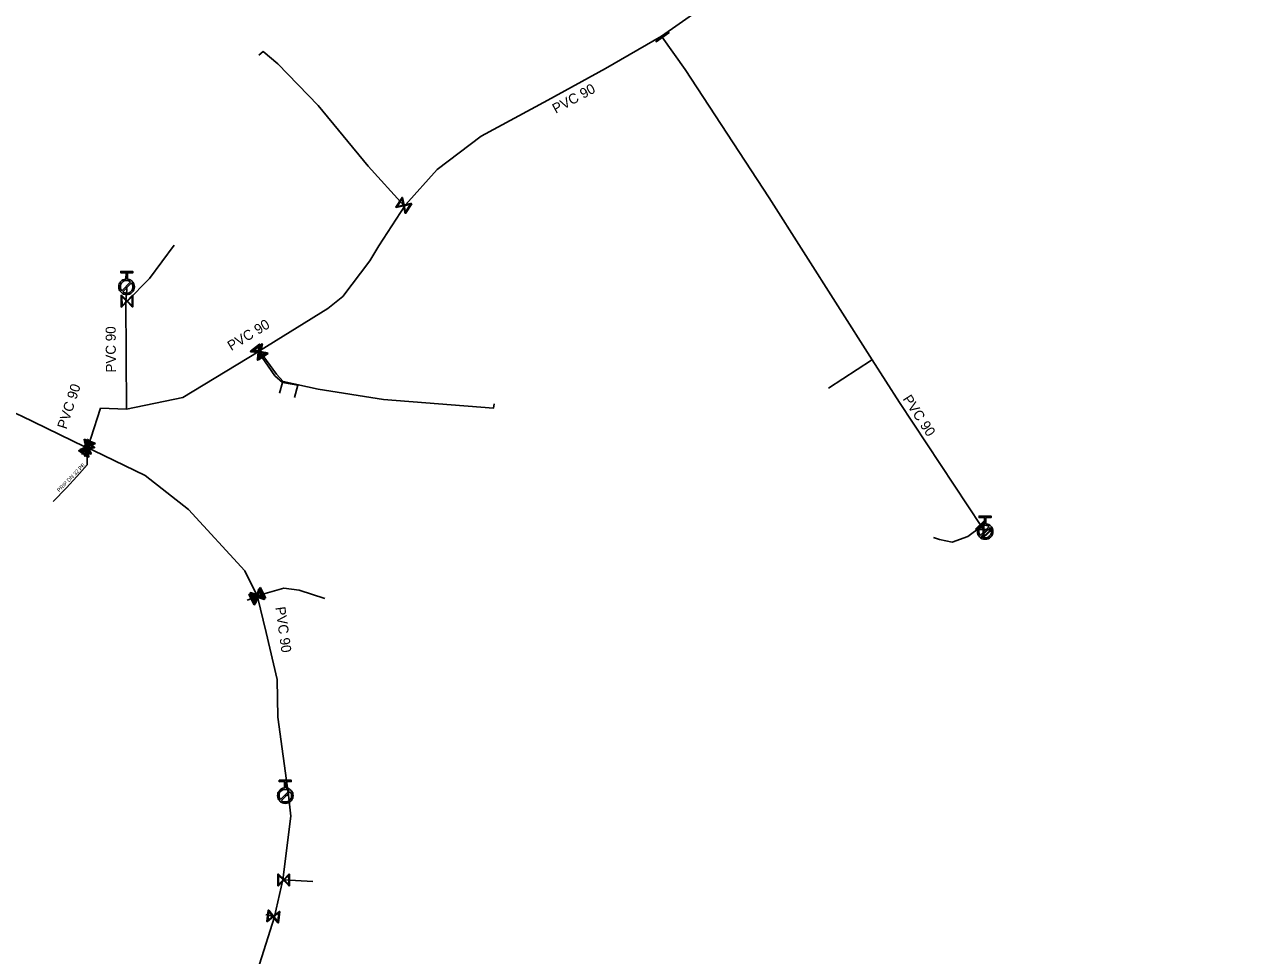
# Model space of a CAD drawing. Extents: x -641905 to -641246, y -1111750 to -1110210.
# Drawn here: x -641426.1 to -641268.6, y -1110592 to -1110471.2 of the extents above; entities that cross this region are included whole.
import ezdxf

# ---------------------------------------------------------------- set-up
doc = ezdxf.new("R2010")
doc.units = 0
for name, color, linetype in [('Default', 7, 'Continuous'), ('VP Hydrant', 7, 'Continuous'), ('VP Popis přípojky', 7, 'Continuous'), ('VP Přípojka', 7, 'Continuous'), ('VP Řad', 7, 'Continuous'), ('VP Řad - popis', 7, 'Continuous'), ('VP Šoupě', 7, 'Continuous')]:
    doc.layers.add(name, color=color, linetype=linetype)

msp = doc.modelspace()

# ---------------------------------------------------------------- linework, layer by layer
at = {"layer": 'Default'}
for points in [[(-641412.72, -1110504.26), (-641412.36, -1110504.3), (-641412.11, -1110504.56), (-641411.82, -1110504.85), (-641411.82, -1110505.27), (-641411.82, -1110505.68), (-641412.12, -1110505.97), (-641412.41, -1110506.26), (-641412.83, -1110506.26), (-641413.24, -1110506.26), (-641413.53, -1110505.96), (-641413.82, -1110505.67), (-641413.82, -1110505.26), (-641413.82, -1110504.84), (-641413.53, -1110504.55), (-641413.27, -1110504.29), (-641412.91, -1110504.26)], [(-641412.31, -1110504.63), (-641412.53, -1110504.45), (-641412.82, -1110504.45), (-641413.16, -1110504.44), (-641413.39, -1110504.68), (-641413.63, -1110504.92), (-641413.63, -1110505.25), (-641413.64, -1110505.55), (-641413.46, -1110505.76)], [(-641413.33, -1110505.89), (-641413.12, -1110506.07), (-641412.83, -1110506.07), (-641412.49, -1110506.07), (-641412.25, -1110505.84), (-641412.01, -1110505.6), (-641412.01, -1110505.26), (-641412.01, -1110504.97), (-641412.18, -1110504.76)], [(-641301.39, -1110535.98), (-641301.03, -1110536.01), (-641300.77, -1110536.27), (-641300.48, -1110536.56), (-641300.48, -1110536.98), (-641300.48, -1110537.39), (-641300.77, -1110537.69), (-641301.06, -1110537.98), (-641301.48, -1110537.98), (-641301.89, -1110537.98), (-641302.18, -1110537.69), (-641302.48, -1110537.4), (-641302.48, -1110536.99), (-641302.48, -1110536.57), (-641302.19, -1110536.28), (-641301.93, -1110536.01), (-641301.58, -1110535.98)], [(-641300.97, -1110536.34), (-641301.19, -1110536.16), (-641301.48, -1110536.17), (-641301.82, -1110536.17), (-641302.06, -1110536.4), (-641302.3, -1110536.64), (-641302.29, -1110536.98), (-641302.29, -1110537.27), (-641302.11, -1110537.49)], [(-641301.99, -1110537.62), (-641301.77, -1110537.79), (-641301.48, -1110537.79), (-641301.14, -1110537.79), (-641300.91, -1110537.55), (-641300.67, -1110537.31), (-641300.67, -1110536.98), (-641300.67, -1110536.69), (-641300.85, -1110536.47)], [(-641392.15, -1110570.23), (-641391.79, -1110570.26), (-641391.53, -1110570.52), (-641391.24, -1110570.81), (-641391.24, -1110571.23), (-641391.24, -1110571.64), (-641391.53, -1110571.93), (-641391.82, -1110572.23), (-641392.24, -1110572.23), (-641392.65, -1110572.23), (-641392.94, -1110571.94), (-641393.24, -1110571.65), (-641393.24, -1110571.24), (-641393.24, -1110570.82), (-641392.95, -1110570.53), (-641392.7, -1110570.26), (-641392.34, -1110570.23)], [(-641391.74, -1110570.59), (-641391.95, -1110570.41), (-641392.25, -1110570.41), (-641392.58, -1110570.42), (-641392.82, -1110570.66), (-641393.06, -1110570.89), (-641393.05, -1110571.23), (-641393.05, -1110571.52), (-641392.87, -1110571.74)], [(-641392.74, -1110571.87), (-641392.53, -1110572.04), (-641392.24, -1110572.04), (-641391.9, -1110572.04), (-641391.66, -1110571.8), (-641391.43, -1110571.56), (-641391.43, -1110571.22), (-641391.43, -1110570.93), (-641391.61, -1110570.72)]]:
    msp.add_open_spline(points, degree=3, dxfattribs=at)
at = {"layer": 'VP Hydrant'}
for points in [[(-641412.91, -1110504.26), (-641412.9, -1110503.44), (-641413.59, -1110503.44), (-641413.59, -1110503.26), (-641412.03, -1110503.26), (-641412.03, -1110503.45), (-641412.72, -1110503.44), (-641412.72, -1110504.26)], [(-641413.46, -1110505.76), (-641412.31, -1110504.63)], [(-641412.18, -1110504.76), (-641413.33, -1110505.89)], [(-641301.58, -1110535.98), (-641301.58, -1110535.16), (-641302.27, -1110535.17), (-641302.27, -1110534.98), (-641300.71, -1110534.98), (-641300.7, -1110535.16), (-641301.39, -1110535.16), (-641301.39, -1110535.98)], [(-641302.11, -1110537.49), (-641300.97, -1110536.34)], [(-641300.85, -1110536.47), (-641301.99, -1110537.62)], [(-641392.34, -1110570.23), (-641392.34, -1110569.41), (-641393.03, -1110569.42), (-641393.03, -1110569.23), (-641391.47, -1110569.23), (-641391.47, -1110569.41), (-641392.16, -1110569.41), (-641392.15, -1110570.23)], [(-641392.87, -1110571.74), (-641391.74, -1110570.59)], [(-641391.61, -1110570.72), (-641392.74, -1110571.87)]]:
    msp.add_lwpolyline(points, dxfattribs=at)
at = {"layer": 'VP Přípojka'}
for points in [[(-641376.76, -1110494.77), (-641376.87, -1110494.7), (-641381.49, -1110489.61), (-641387.97, -1110481.76), (-641393.23, -1110476.33), (-641395.13, -1110474.77), (-641395.66, -1110475.22)], [(-641409.87, -1110504.2), (-641406.64, -1110499.85)], [(-641412.92, -1110507.12), (-641412.77, -1110507.12), (-641409.87, -1110504.2)], [(-641395.76, -1110513.68), (-641395.72, -1110513.73), (-641393.61, -1110516.81)], [(-641395.57, -1110513.56), (-641395.49, -1110513.68), (-641393.37, -1110516.57), (-641392.52, -1110517.52), (-641387.97, -1110518.51), (-641379.5, -1110519.88), (-641365.23, -1110520.98), (-641365.16, -1110520.45)], [(-641316.12, -1110514.73), (-641316.21, -1110514.79), (-641321.8, -1110518.42)], [(-641393.61, -1110516.81), (-641392.61, -1110517.66), (-641393, -1110519.05)], [(-641392.61, -1110517.66), (-641390.63, -1110518.02), (-641391.05, -1110519.59)], [(-641422.35, -1110533.08), (-641420.64, -1110531.32), (-641419.3, -1110529.84), (-641417.95, -1110528.36), (-641418, -1110526.3), (-641417.95, -1110526.12)], [(-641301.94, -1110536.32), (-641302.05, -1110536.39), (-641303.72, -1110537.65), (-641305.74, -1110538.37), (-641307.41, -1110538.03), (-641308.18, -1110537.77)], [(-641395.9, -1110545.32), (-641395.77, -1110545.26), (-641392.42, -1110544.34), (-641390.45, -1110544.6), (-641387.11, -1110545.68)], [(-641395.85, -1110545.41), (-641395.97, -1110545.46), (-641397.2, -1110545.87)], [(-641392.24, -1110571.23), (-641391.83, -1110571.17)], [(-641392.58, -1110582.16), (-641392.45, -1110582.16), (-641388.69, -1110582.34)], [(-641393.64, -1110586.94), (-641394.75, -1110586.65)]]:
    msp.add_lwpolyline(points, dxfattribs=at)
at = {"layer": 'VP Řad'}
for points in [[(-641268.93, -1110412.03), (-641268.93, -1110412.04), (-641268.75, -1110412.33), (-641268.6, -1110412.47), (-641269.23, -1110412.9), (-641269.78, -1110413.28), (-641271.48, -1110414.44), (-641280.76, -1110420.83), (-641284.67, -1110424.02), (-641285.41, -1110424.61), (-641292.73, -1110430.56), (-641293.83, -1110431.65), (-641299.41, -1110437.17), (-641305.81, -1110442.86), (-641309.42, -1110445.79), (-641330.99, -1110463.31), (-641338.43, -1110469.25), (-641343.44, -1110472.77)], [(-641412.84, -1110521.12), (-641405.52, -1110519.61), (-641395.76, -1110513.68), (-641395.57, -1110513.56), (-641386.72, -1110508.07), (-641384.77, -1110506.5), (-641381.3, -1110501.9), (-641380.13, -1110499.95), (-641376.76, -1110494.77), (-641376.66, -1110494.62), (-641372.56, -1110490.07), (-641366.85, -1110485.74), (-641358.2, -1110481.05), (-641350.7, -1110476.97), (-641343.44, -1110472.77)], [(-641343.44, -1110472.77), (-641343.35, -1110472.87), (-641340.39, -1110477.07), (-641329.49, -1110493.73), (-641316.12, -1110514.73), (-641312.58, -1110520.24), (-641301.94, -1110536.32), (-641301.68, -1110536.72), (-641301.48, -1110536.98)], [(-641412.82, -1110505.26), (-641412.78, -1110505.64), (-641412.92, -1110507.12), (-641412.84, -1110521.12)], [(-641479.47, -1110506.59), (-641479.27, -1110506.62), (-641472.51, -1110507.72), (-641464.49, -1110508.41), (-641457.56, -1110509.13), (-641450.89, -1110510.61), (-641442.5, -1110512.82), (-641438.36, -1110515.06), (-641435.23, -1110517.02), (-641429.22, -1110520.79), (-641426.48, -1110522), (-641418.24, -1110525.99), (-641418.01, -1110526.1), (-641417.95, -1110526.12)], [(-641417.95, -1110526.12), (-641417.93, -1110526.05), (-641417.9, -1110525.97), (-641417.48, -1110524.9), (-641416.2, -1110521), (-641412.84, -1110521.12)], [(-641417.95, -1110526.12), (-641417.84, -1110526.15), (-641417.1, -1110526.46)], [(-641406.62, -1110609.5), (-641406.42, -1110609.23), (-641406.35, -1110609.14), (-641406.3, -1110609.07), (-641406.23, -1110608.97), (-641398.89, -1110599.95), (-641395.57, -1110593.08), (-641393.64, -1110586.94), (-641393.63, -1110586.92), (-641392.58, -1110582.16), (-641391.51, -1110573.9), (-641391.83, -1110571.17), (-641393.23, -1110561.05), (-641393.28, -1110556.19), (-641394.73, -1110550.07), (-641395.83, -1110545.45), (-641395.85, -1110545.41), (-641395.9, -1110545.32), (-641397.5, -1110542.1), (-641404.8, -1110534.12), (-641410.42, -1110529.73), (-641417.1, -1110526.46)]]:
    msp.add_lwpolyline(points, dxfattribs=at)
at = {"layer": 'VP Šoupě'}
for points in [[(-641344.21, -1110473.39), (-641342.56, -1110472.25), (-641342.49, -1110472.35), (-641344.14, -1110473.49), (-641344.21, -1110473.39)], [(-641375.83, -1110494.48), (-641376.65, -1110495.74), (-641376.7, -1110495.7), (-641376.73, -1110495.57), (-641376.9, -1110494.75), (-641377.85, -1110494.96), (-641377.91, -1110494.92), (-641377.09, -1110493.66), (-641377.04, -1110493.7), (-641376.84, -1110494.65), (-641376.01, -1110494.47), (-641375.89, -1110494.44), (-641375.83, -1110494.48)], [(-641377.75, -1110494.84), (-641376.92, -1110494.67), (-641377.1, -1110493.84), (-641377.75, -1110494.84)], [(-641376, -1110494.56), (-641376.82, -1110494.74), (-641376.64, -1110495.55), (-641376, -1110494.56)], [(-641412.03, -1110506.37), (-641412.02, -1110507.87), (-641412.08, -1110507.87), (-641412.17, -1110507.77), (-641412.77, -1110507.18), (-641413.45, -1110507.87), (-641413.52, -1110507.88), (-641413.53, -1110506.38), (-641413.46, -1110506.37), (-641412.77, -1110507.06), (-641412.18, -1110506.46), (-641412.09, -1110506.37), (-641412.03, -1110506.37)], [(-641413.42, -1110507.72), (-641412.83, -1110507.12), (-641413.43, -1110506.53), (-641413.42, -1110507.72)], [(-641412.12, -1110506.52), (-641412.71, -1110507.12), (-641412.11, -1110507.71), (-641412.12, -1110506.52)], [(-641394.66, -1110513.85), (-641395.84, -1110514.79), (-641395.88, -1110514.73), (-641395.86, -1110514.61), (-641395.77, -1110513.77), (-641396.73, -1110513.67), (-641396.77, -1110513.61), (-641395.6, -1110512.68), (-641395.56, -1110512.73), (-641395.67, -1110513.69), (-641394.83, -1110513.79), (-641394.71, -1110513.8), (-641394.66, -1110513.85)], [(-641396.6, -1110513.59), (-641395.76, -1110513.68), (-641395.67, -1110512.85), (-641396.6, -1110513.59)], [(-641394.46, -1110513.92), (-641395.73, -1110514.71), (-641395.77, -1110514.66), (-641395.73, -1110514.53), (-641395.54, -1110513.71), (-641396.49, -1110513.49), (-641396.52, -1110513.44), (-641395.25, -1110512.65), (-641395.21, -1110512.7), (-641395.44, -1110513.65), (-641394.62, -1110513.84), (-641394.49, -1110513.87), (-641394.46, -1110513.92)], [(-641396.34, -1110513.44), (-641395.52, -1110513.63), (-641395.33, -1110512.81), (-641396.34, -1110513.44)], [(-641394.85, -1110513.87), (-641395.68, -1110513.78), (-641395.77, -1110514.61), (-641394.85, -1110513.87)], [(-641394.64, -1110513.93), (-641395.46, -1110513.73), (-641395.65, -1110514.55), (-641394.64, -1110513.93)], [(-641418.24, -1110525.27), (-641416.97, -1110526.06), (-641417, -1110526.12), (-641417.13, -1110526.14), (-641417.95, -1110526.33), (-641417.72, -1110527.28), (-641417.76, -1110527.33), (-641419.03, -1110526.54), (-641419, -1110526.48), (-641418.05, -1110526.27), (-641418.24, -1110525.45), (-641418.28, -1110525.32), (-641418.24, -1110525.27)], [(-641418.31, -1110525), (-641416.92, -1110525.55), (-641416.94, -1110525.61), (-641417.06, -1110525.66), (-641417.83, -1110526), (-641417.44, -1110526.88), (-641417.46, -1110526.95), (-641418.86, -1110526.4), (-641418.84, -1110526.34), (-641417.95, -1110525.95), (-641418.28, -1110525.18), (-641418.34, -1110525.06), (-641418.31, -1110525)], [(-641417.57, -1110526.8), (-641417.91, -1110526.03), (-641418.68, -1110526.37), (-641417.57, -1110526.8)], [(-641418.67, -1110526.89), (-641417.91, -1110525.04), (-641417.8, -1110525.09), (-641418.56, -1110526.94), (-641418.67, -1110526.89)], [(-641417.37, -1110525.39), (-641418.18, -1110527.22), (-641418.29, -1110527.17), (-641417.49, -1110525.34), (-641417.37, -1110525.39)], [(-641418.2, -1110525.15), (-641417.86, -1110525.92), (-641417.1, -1110525.58), (-641418.2, -1110525.15)], [(-641418.16, -1110525.43), (-641417.97, -1110526.25), (-641417.15, -1110526.06), (-641418.16, -1110525.43)], [(-641417.84, -1110527.17), (-641418.03, -1110526.35), (-641418.85, -1110526.54), (-641417.84, -1110527.17)], [(-641302.74, -1110536.69), (-641301.65, -1110535.66), (-641301.6, -1110535.71), (-641301.61, -1110535.84), (-641301.64, -1110536.68), (-641300.66, -1110536.71), (-641300.62, -1110536.75), (-641301.71, -1110537.78), (-641301.76, -1110537.73), (-641301.73, -1110536.76), (-641302.57, -1110536.74), (-641302.7, -1110536.73), (-641302.74, -1110536.69)], [(-641302.56, -1110536.65), (-641301.72, -1110536.67), (-641301.7, -1110535.84), (-641302.56, -1110536.65)], [(-641300.8, -1110536.79), (-641301.64, -1110536.76), (-641301.66, -1110537.6), (-641300.8, -1110536.79)], [(-641395.65, -1110544.44), (-641394.94, -1110545.77), (-641395, -1110545.8), (-641395.12, -1110545.76), (-641395.93, -1110545.51), (-641396.21, -1110546.44), (-641396.27, -1110546.47), (-641396.97, -1110545.15), (-641396.91, -1110545.12), (-641395.98, -1110545.4), (-641395.74, -1110544.6), (-641395.7, -1110544.48), (-641395.65, -1110544.44)], [(-641395.48, -1110544.26), (-641394.8, -1110545.6), (-641394.86, -1110545.63), (-641394.98, -1110545.59), (-641395.78, -1110545.33), (-641396.08, -1110546.25), (-641396.14, -1110546.28), (-641396.82, -1110544.94), (-641396.76, -1110544.91), (-641395.84, -1110545.21), (-641395.57, -1110544.42), (-641395.54, -1110544.29), (-641395.48, -1110544.26)], [(-641396.13, -1110546.1), (-641395.86, -1110545.3), (-641396.66, -1110545.04), (-641396.13, -1110546.1)], [(-641395.65, -1110544.63), (-641395.9, -1110545.43), (-641395.1, -1110545.67), (-641395.65, -1110544.63)], [(-641395.49, -1110544.45), (-641395.75, -1110545.24), (-641394.96, -1110545.5), (-641395.49, -1110544.45)], [(-641396.26, -1110546.29), (-641396.01, -1110545.49), (-641396.81, -1110545.24), (-641396.26, -1110546.29)], [(-641391.7, -1110581.41), (-641391.7, -1110582.91), (-641391.77, -1110582.91), (-641391.85, -1110582.82), (-641392.45, -1110582.22), (-641393.13, -1110582.91), (-641393.2, -1110582.91), (-641393.2, -1110581.41), (-641393.13, -1110581.41), (-641392.45, -1110582.1), (-641391.86, -1110581.5), (-641391.77, -1110581.41), (-641391.7, -1110581.41)], [(-641393.11, -1110582.76), (-641392.51, -1110582.16), (-641393.11, -1110581.57), (-641393.11, -1110582.76)], [(-641391.79, -1110581.57), (-641392.39, -1110582.16), (-641391.79, -1110582.75), (-641391.79, -1110581.57)], [(-641392.97, -1110586.24), (-641393.14, -1110587.73), (-641393.21, -1110587.72), (-641393.28, -1110587.62), (-641393.81, -1110586.96), (-641394.57, -1110587.56), (-641394.63, -1110587.56), (-641394.46, -1110586.07), (-641394.39, -1110586.07), (-641393.79, -1110586.84), (-641393.13, -1110586.32), (-641393.03, -1110586.23), (-641392.97, -1110586.24)], [(-641394.52, -1110587.42), (-641393.86, -1110586.89), (-641394.38, -1110586.23), (-641394.52, -1110587.42)], [(-641393.08, -1110586.39), (-641393.74, -1110586.91), (-641393.22, -1110587.56), (-641393.08, -1110586.39)]]:
    msp.add_lwpolyline(points, dxfattribs=at)

# ---------------------------------------------------------------- texts
at = {"layer": 'VP Popis přípojky'}
msp.add_text('PRIP DN 32 PE', height=0.5, rotation=45.8255, dxfattribs=at).set_placement((-641421.55, -1110531.91))
at = {"layer": 'VP Řad - popis'}
for rotation, p in [(28.5462, (-641357.17, -1110482.84)), (90.3274, (-641414.21, -1110516.37)), (31.2821, (-641399.25, -1110513.6)), (71.8299, (-641420.63, -1110523.8)), (303.4823, (-641312.23, -1110519.8)), (277.8763, (-641393.54, -1110546.82))]:
    msp.add_text('PVC 90', height=1.3, rotation=rotation, dxfattribs=at).set_placement(p)

doc.saveas('drawing.dxf')
